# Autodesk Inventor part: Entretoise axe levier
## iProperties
Author: Flavien MARTY
Shininess: 86.0
PropertySet Name: _Private Model Information
Created: 2001-10
Part Number: Entretoise axe levier
Material: Par défaut
Document SubType Name: Modélisation
Designer: Flavien MARTY
Control State: 0
Master: False
Checked Out: False
PropertySet Name: Design Tracking Control
Density: 0.0
Volumn: 0.0
Area: 0.0
PropertySet Name: Model Information
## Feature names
1. Base1
